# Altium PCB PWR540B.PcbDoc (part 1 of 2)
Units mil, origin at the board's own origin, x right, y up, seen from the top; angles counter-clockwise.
Board outline 2790 x 2490 mil, 4 copper layers (Top Layer, MidLayer1, MidLayer2, Bottom Layer), stack 95.6 mil thick; 144 components, 56 nets, 352 pads, 322 vias.
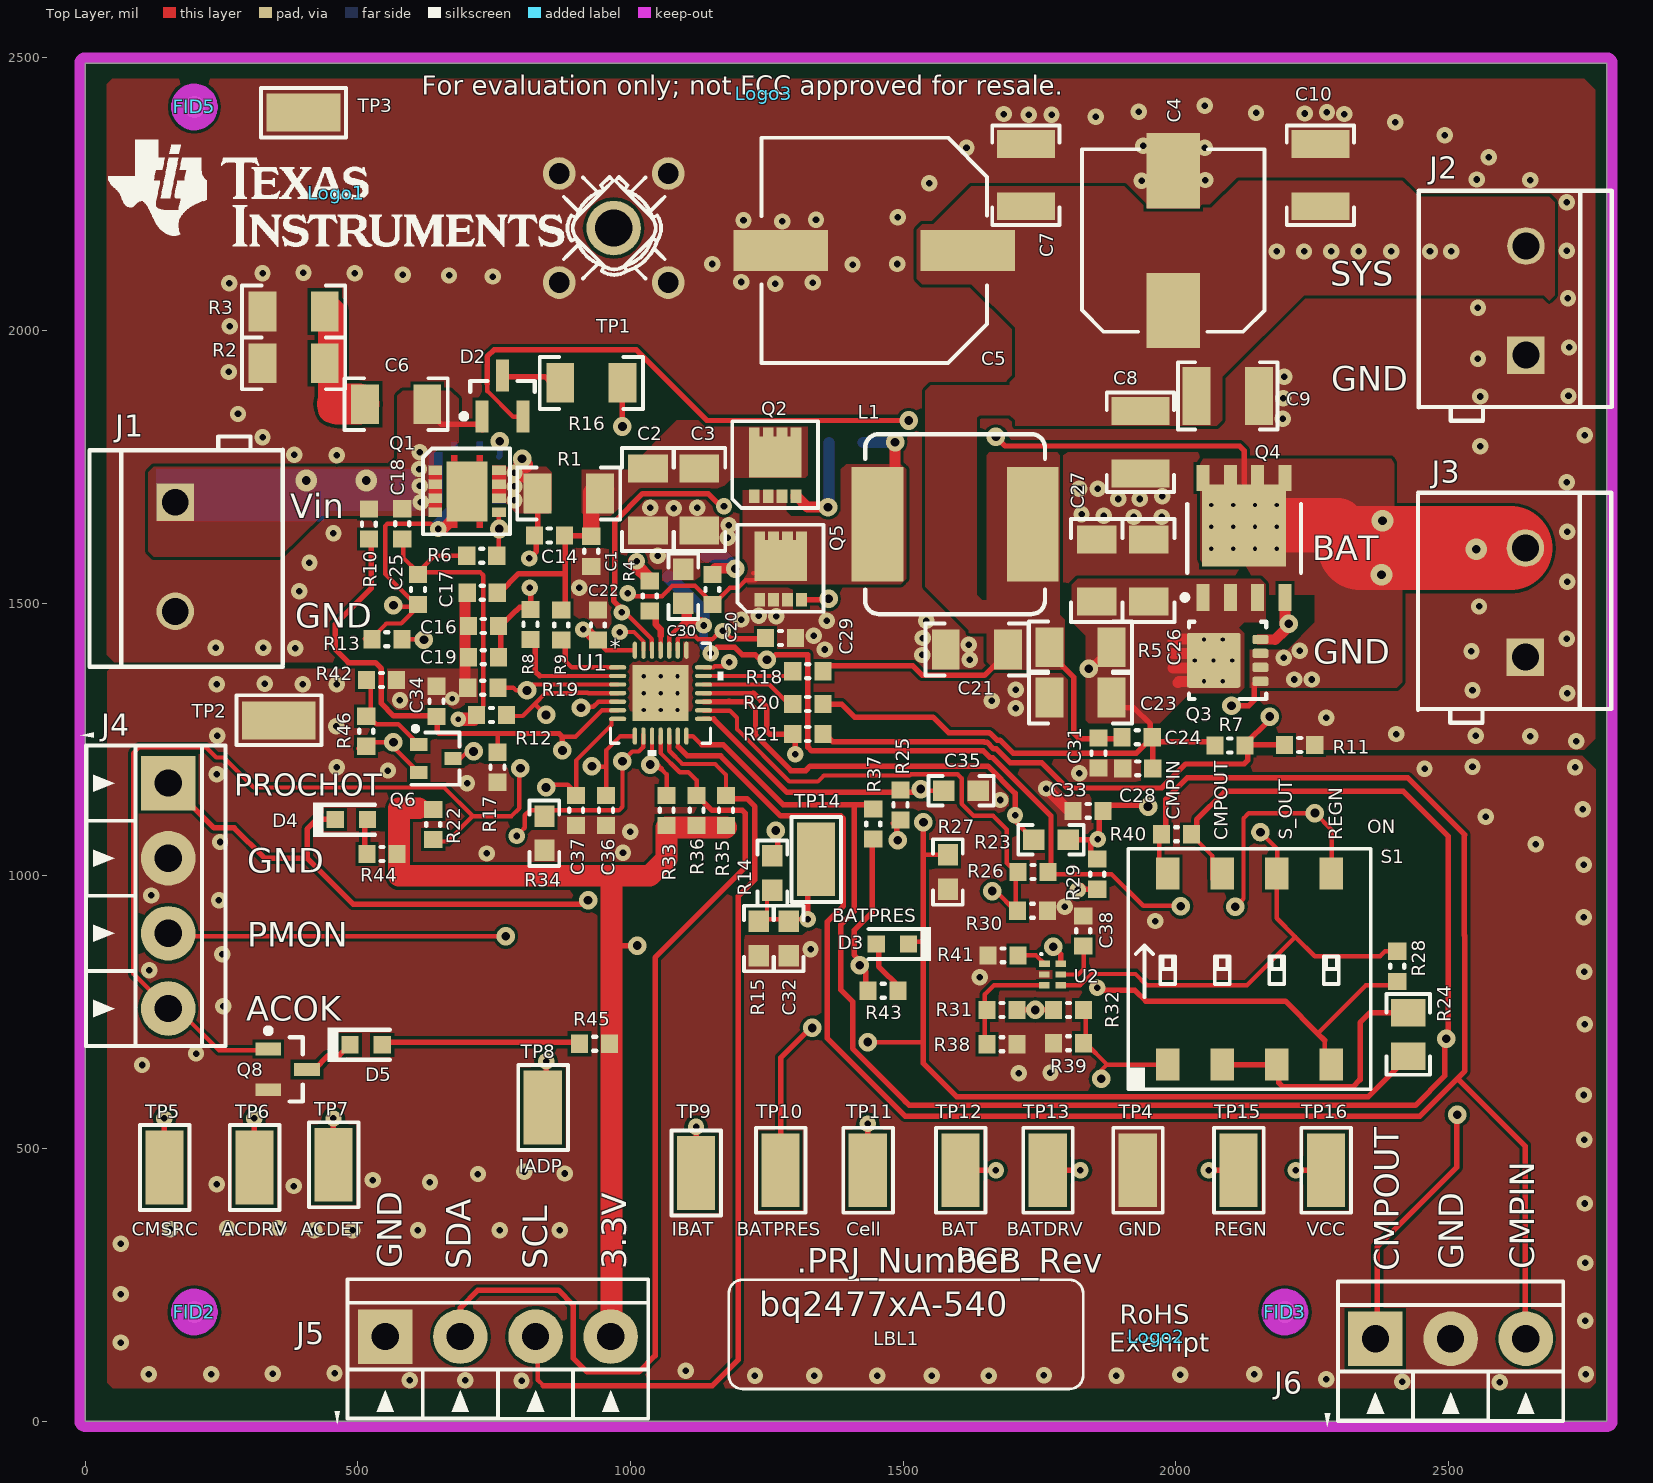
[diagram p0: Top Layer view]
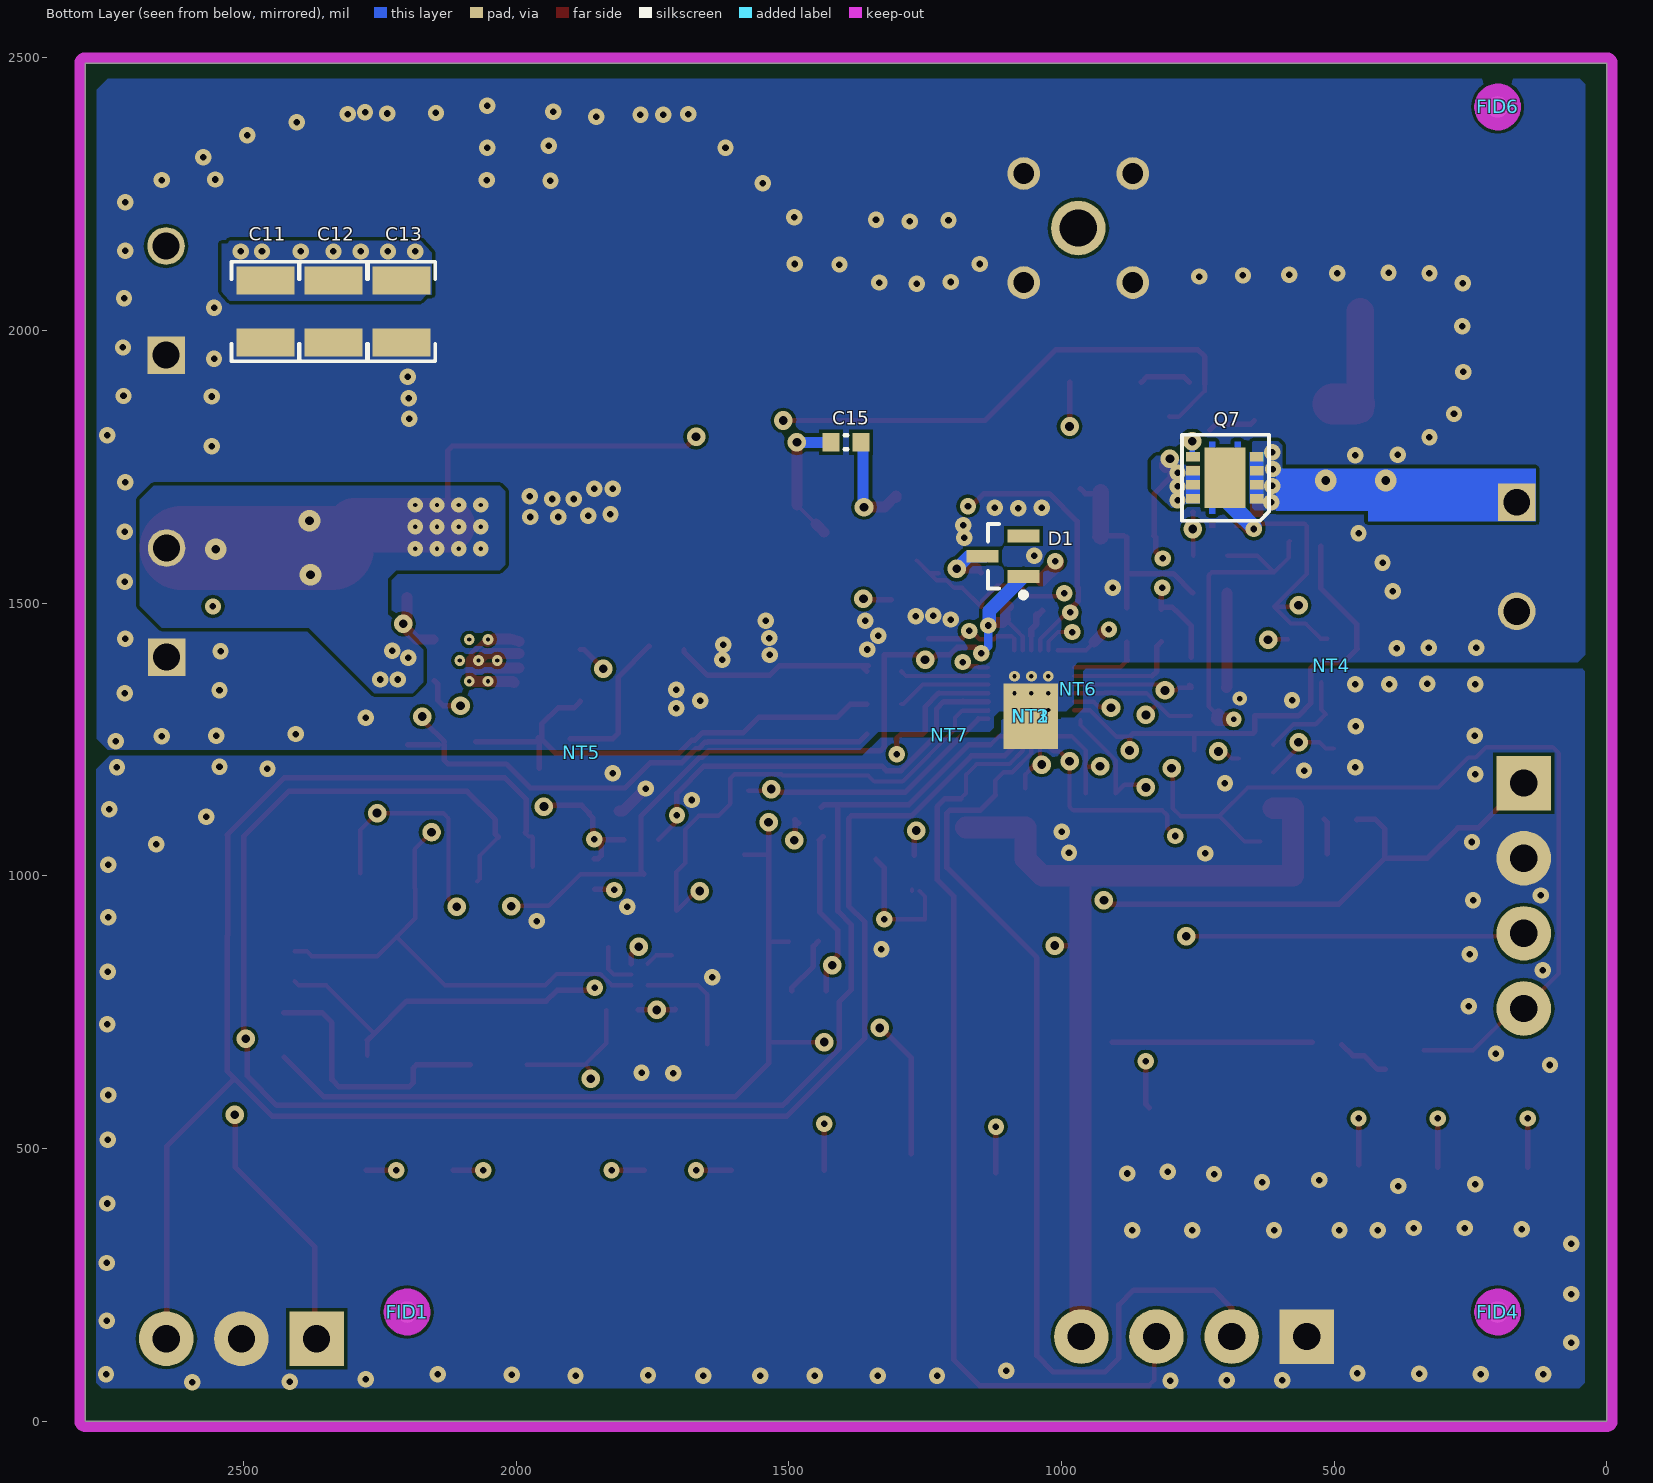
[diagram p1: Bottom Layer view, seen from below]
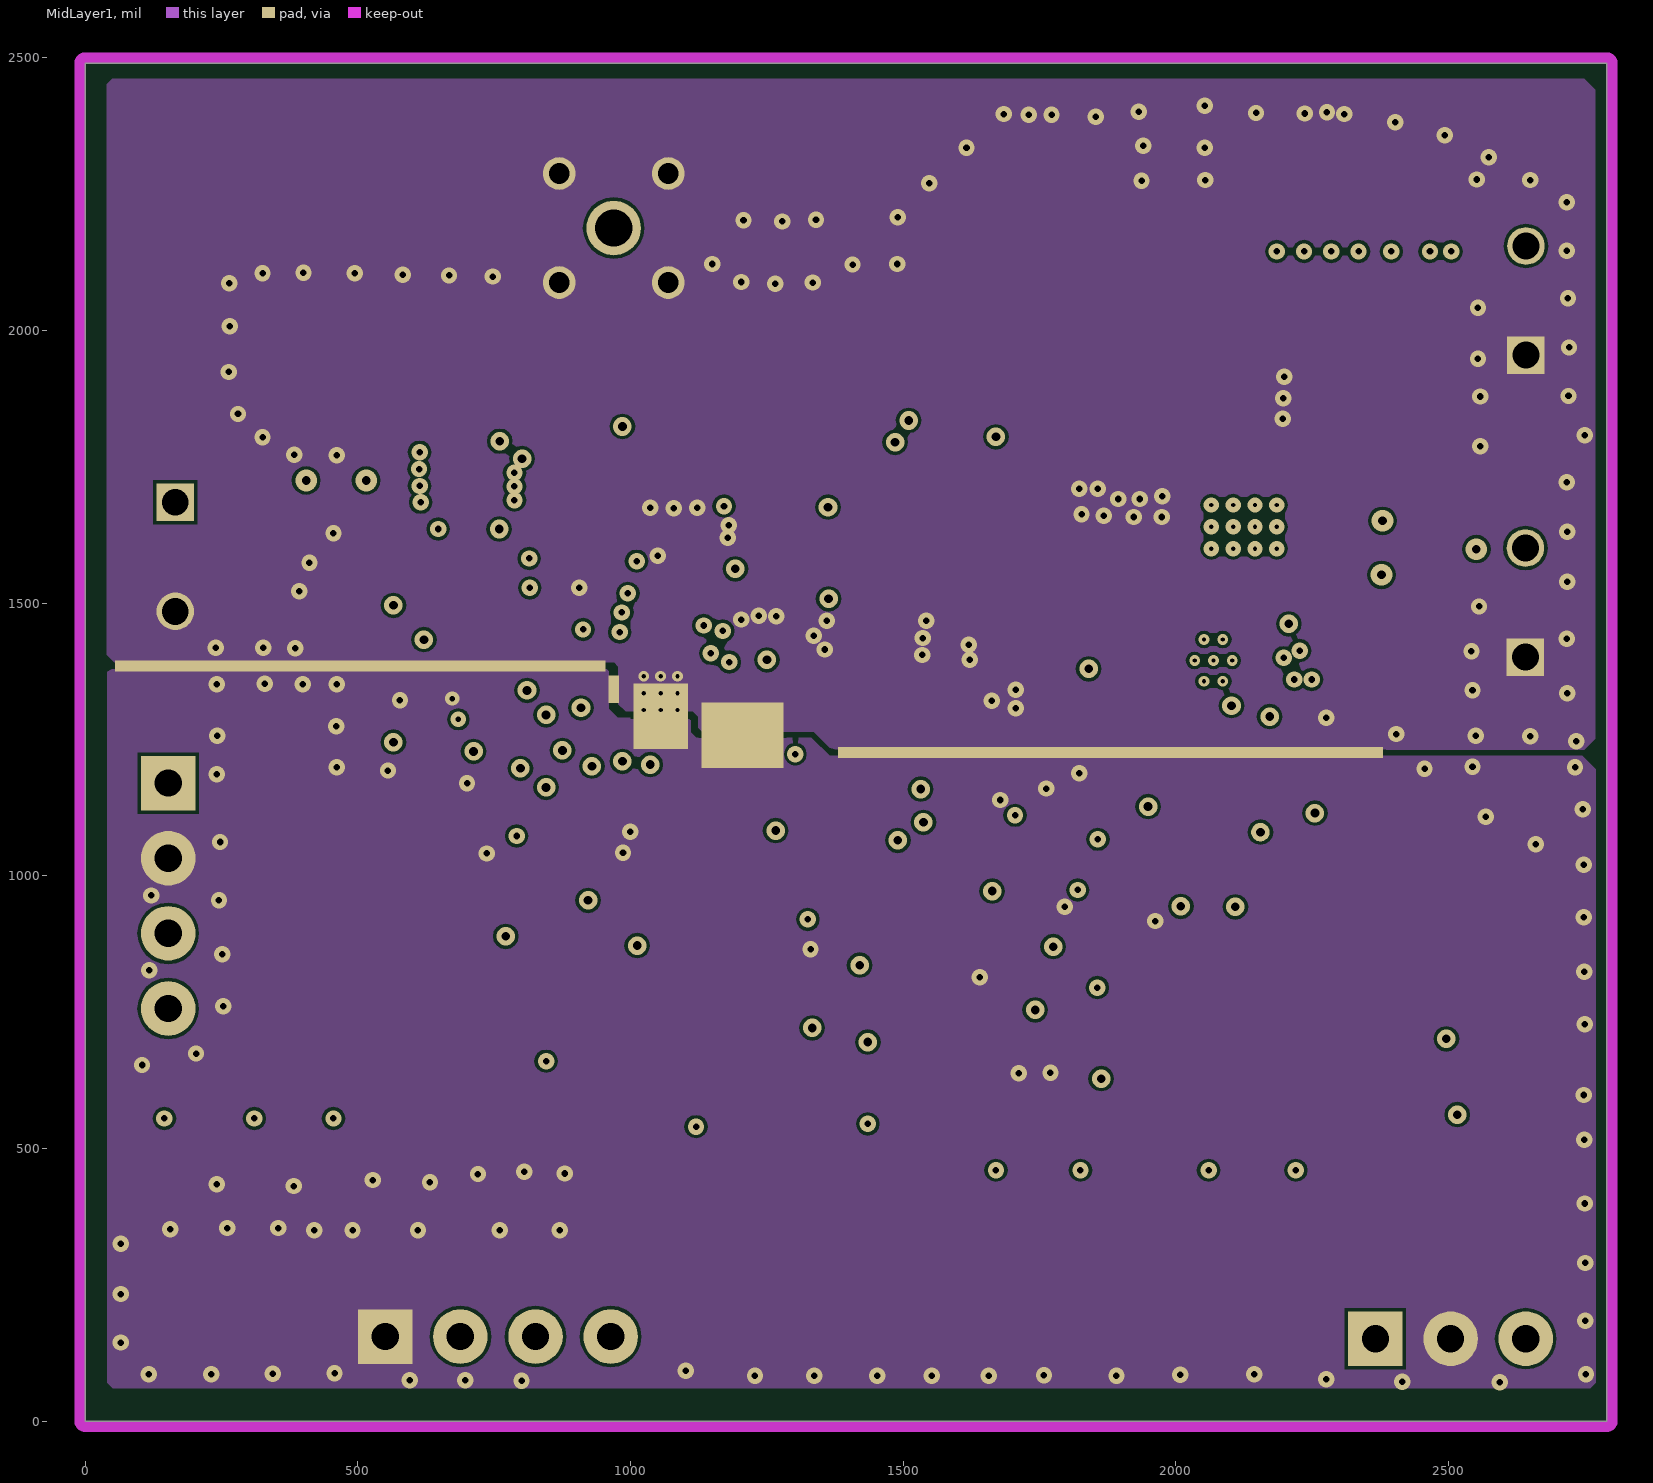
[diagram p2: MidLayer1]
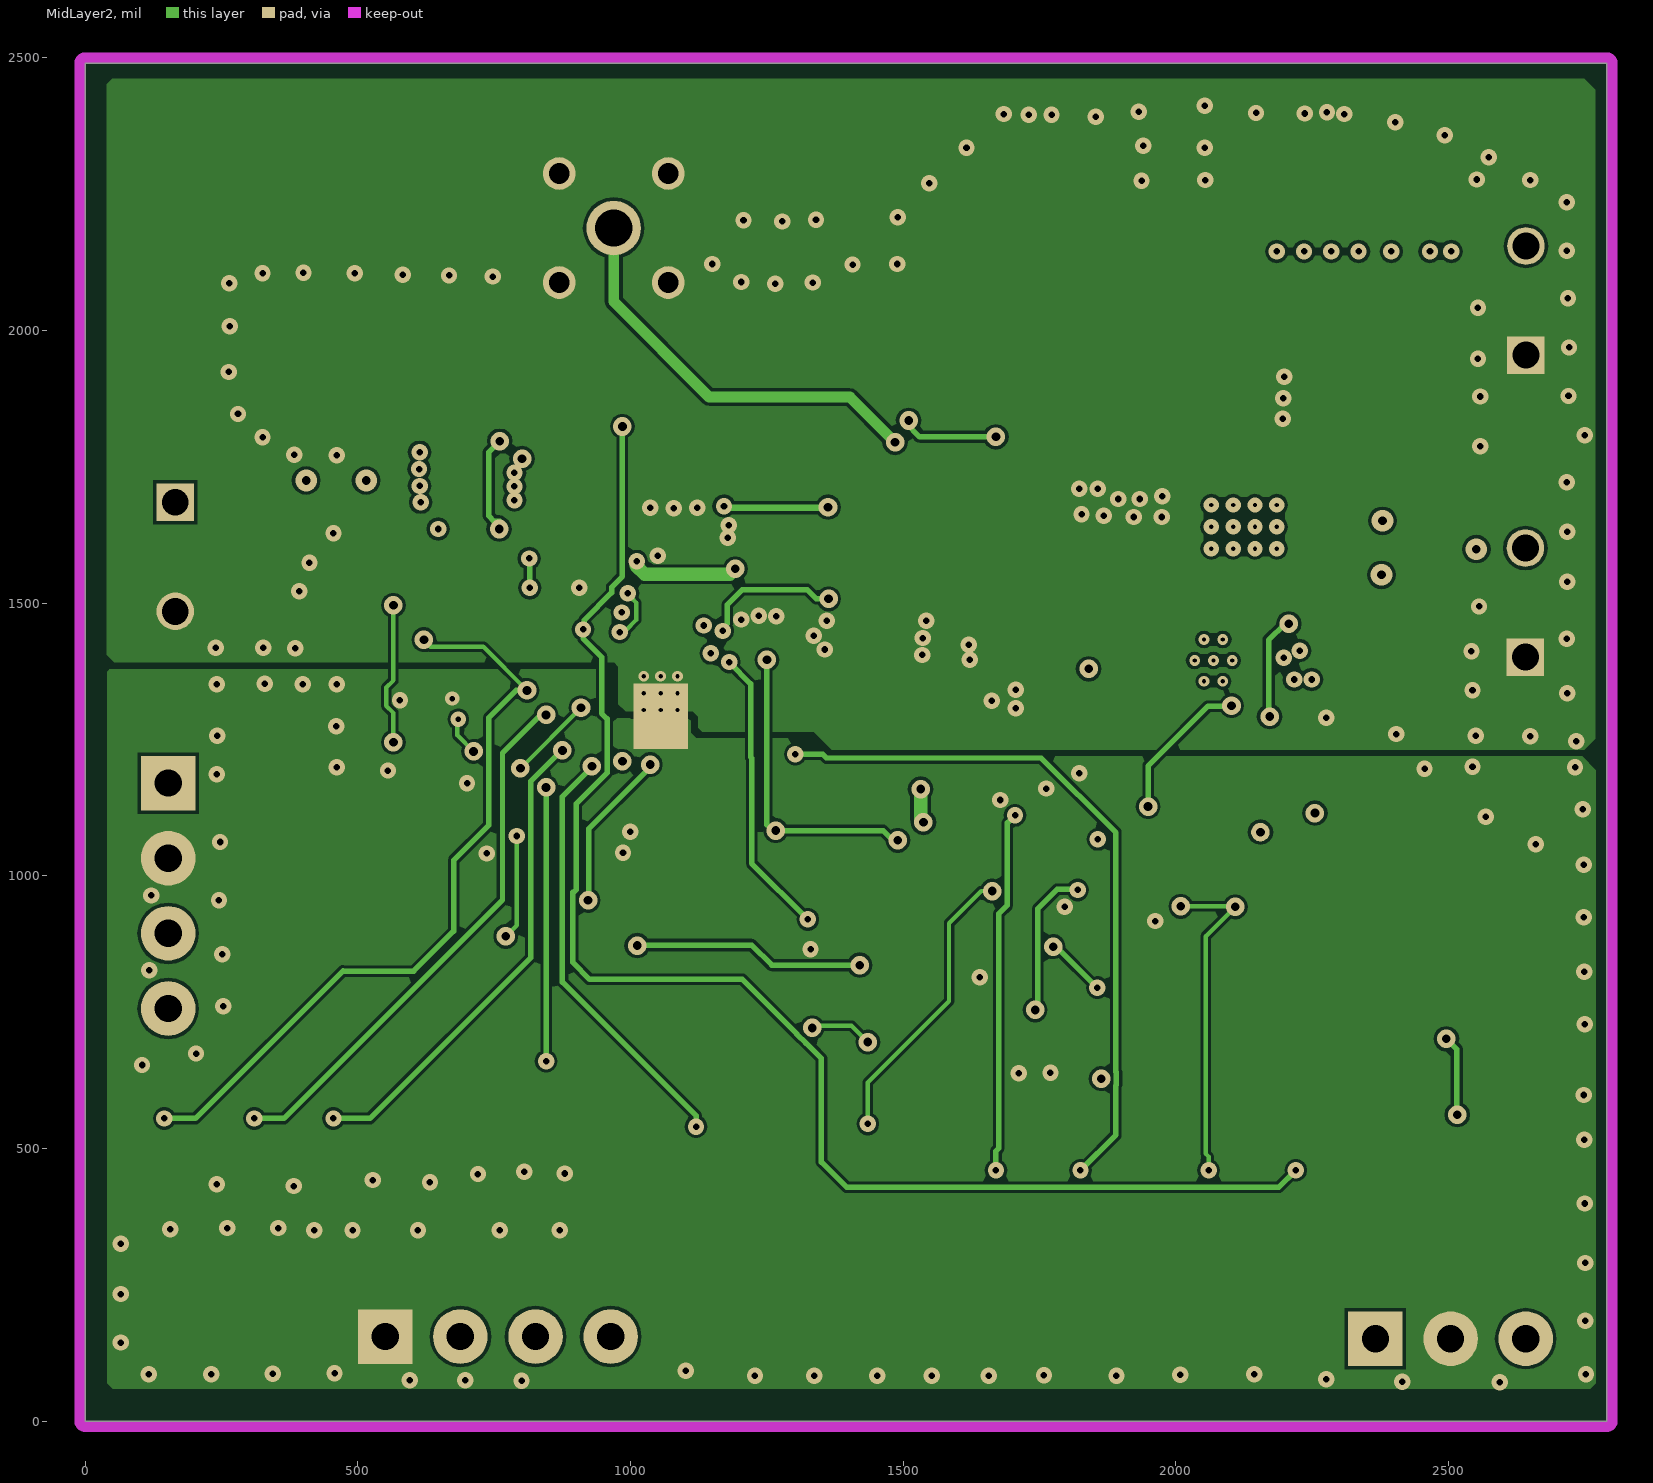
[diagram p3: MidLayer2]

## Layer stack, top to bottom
Top Solder: solder mask 0.4, Solder Resist, Dk 3.5
Top Layer: signal copper 2.8
Dielectric1: core 59.2, FR-4, Dk 4.8
MidLayer1: signal copper 2.8
Dielectric2: prepreg 12.6, FR-4, Dk 4.8
MidLayer2: signal copper 2.8
Dielectric3: core 12.6, FR-4, Dk 4.8
Bottom Layer: signal copper 2.8
Bottom Solder: solder mask 0.4, Solder Resist, Dk 3.5

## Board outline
0,0 0,2490 2790,2490 2790,0

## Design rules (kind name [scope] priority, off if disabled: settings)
AcuteAngle [All] p1: minimum=4.50000000000000E+0001 checktracksonly=FALSE
AssemblyTestPointUsage [All] p1: valid=2
AssemblyTestpoint [All] p1: testpointundercomponent=TRUE minsize=40 maxsize=100 preferedsize=30 minholesize=0 maxholesize=40 preferedholesize=12 testpointgrid=1 usegrid=TRUE gridtolerance=0.01 allowsidetop=TRUE allowsidebottom=TRUE
Clearance EVM [All] p1: gap=5.9 // TEST1
Clearance Clearance_BoardEdge_MountingHoles [OnCopper and InComponentClass('Mounting Holes') vs IsKeepOut] p2: gap=40
Clearance Clearance_BoardEdge_Poly [OnCopper and InPoly vs IsKeepOut] p3: gap=25
Clearance Clearance_BoardEdge [OnCopper and Not InComponentClass('Logo') and not InComponentClass('FiducialMark') and not InRegion(1000,500,4000,800) and Not IsKeepout vs IsKeepOut] p4: gap=25
Clearance [All] p5: gap=6
ComponentClearance ComponentClearance_NT [InComponent('NT*')] p1: gap=0 collisioncheckmode=3 verticalgap=0 showdistances=FALSE
ComponentClearance ComponentClearance_Logo [InComponentClass('Logo')] p2: gap=0 collisioncheckmode=3 verticalgap=0 showdistances=FALSE
ComponentClearance ComponentClearance_ScrewToNut [(HasFootprint('NY PMS 440 0025 PH')) vs (HasFootprint('Keystone_1902C'))] p3: gap=5 collisioncheckmode=3 verticalgap=10 showdistances=FALSE
ComponentClearance ComponentClearance_MountingHoles [InComponentClass('Mounting Holes')] p4: gap=50 collisioncheckmode=3 verticalgap=100000 showdistances=FALSE
ComponentClearance ComponentClearance_SmallPassives [HasFootprint('0201*') or HasFootprint('0402*') or HasFootprint('0508') or HasFootprint('0603*') or HasFootprint('0612') or HasFootprint('0805*') or HasFootprint('0815*') or HasFootprint('0830*') or HasFootprint('1206*') or HasFootprint('1210*') or HasFootprint('1808*') or HasFootprint('1812*') or HasFootprint('1825*') or HasFootprint('2010*') or HasFootprint('2220*') or HasFootprint('2225*') or HasFootprint('2512*') or HasFootprint('2728*') or HasFootprint('3518*') vs HasFootprint('0201*') or HasFootprint('0402*') or HasFootprint('0508') or HasFootprint('0603*') or HasFootprint('0612') or HasFootprint('0805*') or HasFootprint('0815*') or HasFootprint('0830*') or HasFootprint('1206*') or HasFootprint('1210*') or HasFootprint('1808*') or HasFootprint('1812*') or HasFootprint('1825*') or HasFootprint('2010*') or HasFootprint('2220*') or HasFootprint('2225*') or HasFootprint('2512*') or HasFootprint('2728*') or HasFootprint('3518*')] p5: gap=10 collisioncheckmode=3 verticalgap=10 showdistances=FALSE
ComponentClearance ComponentClearance_THtoSMT [IsThruComponent vs IsSMTComponent and not InComponentClass('Logo')] p6: gap=1 collisioncheckmode=3 verticalgap=0 showdistances=FALSE
ComponentClearance ComponentClearance_THtoTH [IsThruComponent vs IsThruComponent] p7: gap=10 collisioncheckmode=3 verticalgap=100000 showdistances=FALSE
ComponentClearance [All] p8: gap=10 collisioncheckmode=3 verticalgap=10 showdistances=FALSE
DiffPairsRouting [All] p1: maxlimit=100 minlimit=10 mostfreqgap=10 toplayer_minwidth=15 toplayer_maxwidth=15 toplayer_prefwidth=15 midlayer1_minwidth=15 midlayer1_maxwidth=15 midlayer1_prefwidth=15 midlayer2_minwidth=15 midlayer2_maxwidth=15 midlayer2_prefwidth=15 bottomlayer_minwidth=15 bottomlayer_maxwidth=15 bottomlayer_prefwidth=15 maxuncoupledlength=1000
FabricationTestPointUsage TestPointUsage [All] p1: valid=2 allowmultiple=FALSE
FabricationTestpoint Testpoint [All] p1: side=3 testpointundercomponent=TRUE minsize=40 maxsize=100 preferedsize=30 minholesize=0 maxholesize=40 preferedholesize=12 testpointgrid=1 allowsidetop=TRUE allowsidebottom=TRUE usegrid=TRUE gridtolerance=0.01
FanoutControl Fanout_LCC [IsLCC] p1: bgadir=Out bgaviamode=Centered fanoutstyle=Auto fanoutdirection=Alternating viagrid=1 // Fanout_LCC (Default Rule)
FanoutControl Fanout_BGA [IsBGA] p2: bgadir=Out bgaviamode=Centered fanoutstyle=Auto fanoutdirection=Alternating viagrid=1 // Fanout_BGA (Default Rule)
FanoutControl Fanout_Default [All] p4: bgadir=Out bgaviamode=Centered fanoutstyle=Auto fanoutdirection=Alternating viagrid=1 // Fanout_Default (Default Rule)
FanoutControl Fanout_Small [(CompPinCount < 5)] p5: bgadir=Out bgaviamode=Centered fanoutstyle=Auto fanoutdirection=OutThenIn viagrid=1 // Fanout_Small (Default Rule)
HoleSize [All] p1: absolutevalues=TRUE maxlimit=251 minlimit=7.8 maxpercent=80.000 minpercent=20.000
MinimumAnnularRing [All] p1: minimumring=5
MinimumSolderMaskSliver MinimumSolderMaskSliver_Logo [InComponentClass('Logo') vs InComponentClass('Logo')] p1: minsoldermaskwidth=0.7
MinimumSolderMaskSliver [All] p2: minsoldermaskwidth=3.9
PlaneConnect [All] p1: planeconnectstyle=Relief reliefexpansion=10 reliefentries=4 reliefconductorwidth=10 reliefairgap=10
PolygonConnect [All] p1: connectstyle=Direct reliefconductorwidth=10 reliefentries=4 polygonreliefangle="90 Angle" airgapwidth=10
RoutingVias [All] p1: holewidth=16 width=34 viastyle="Through Hole" minholewidth=7 minwidth=19 maxholewidth=40 maxwidth=65
SMDToCorner [All] p1 off: distance=30000
SilkToSilkClearance "SilkToSilkClearance_pbfree logo" [InComponent('Logo2') vs InComponent('Logo2')] p1: silktosilkclearance=0
SilkToSilkClearance [All] p2: silktosilkclearance=3
SilkToSolderMaskClearance SilkToSolderMaskClearance_fet [HasFootprint('TRANS_NexFET_Q3E')] p1: minsilkscreentomaskgap=0.5 clearancetoexposedcopper=TRUE
SilkToSolderMaskClearance [IsPad] p2: minsilkscreentomaskgap=3 clearancetoexposedcopper=TRUE
SolderMaskExpansion [All] p1: expansion=1
Width [All] p1: maxlimit=250 minlimit=7.8 preferedwidth=10 checkconnectedcopper=TRUE
15 further rules are at their usual default settings.

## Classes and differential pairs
component class Logo: Logo1
component class PWR540B_Hardware: FID1 FID2 FID3 FID4 FID5 FID6 LBL1 Logo1 Logo2 Logo3 ZZ1 ZZ2 ZZ3 ZZ4
component class PWR540B: C1 C2 C3 C4 C5 C6 C7 C8 C9 C10 C11 C12 C13 C14 C15 C16 C17 C18 C19 C20 C21 C22 C23 C24 C25 C26 C27 C28 C29 C30 C31 C32 C33 C34 C35 C36 C37 C38 C52 D1 D2 D3 D4 D5 J1 J2 J3 J4 J5 J6 L1 NT1 NT2 NT3 NT4 NT5 NT6 NT7 Q1 Q2 Q3 Q4 Q5 Q6 Q7 Q8 Q52 R1 R2 R3 R4 R5 R6 R7 R8 R9 R10 R11 R12 R13 R14 R15 R16 R17 R18 R19 R20 R21 R22 R23 R24 R25 R26 R27 R28 R29 R30 R31 R32 R33 R34 R35 R36 R37 R38 R39 R40 R41 R42 R43 R44 R45 R46 S1 TP1 TP2 TP3 TP4 TP5 TP6 TP7 TP8 TP9 TP10 TP11 TP12 TP13 TP14 TP15 TP16 U1 U2
component class FiducialMark: FID1 FID2 FID3 FID4 FID5 FID6
component class AssemblyNote: ZZ1 ZZ2 ZZ3 ZZ4
component class Label: LBL1

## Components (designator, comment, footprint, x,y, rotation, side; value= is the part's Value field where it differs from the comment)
C1 "GRM188R71E105KA12D" 0603L 928,1595 r270 top
C2 "GRM31CR61E106KA12L" 1206 1032,1690 r270 top
C3 "GRM31CR61E106KA12L" 1206 1126,1690 r270 top
C4 "20SVP100M" SM_RADIAL_8MM 1995,2165 r90 top
C5 "16SVP100M" SM_RADIAL_10AMM 1447,2147 r180 top
C6 "GRM31MR71E225KA93L" 1206 570,1865 r180 top
C7 "GRM32ER61E226KE15L" 1210 1725,2285 r90 top
C8 "GRM32ER61E226KE15L" 1210 1935,1795 r270 top
C9 "GRM32ER61E226KE15L" 1210 2095,1880 r0 top
C10 "GRM32ER61E226KE15L" 1210 2265,2285 r90 top
C11 "GRM32ER61E226KE15L" 1210 2460,2035 r270 bottom
C12 "GRM32ER61E226KE15L" 1210 2335,2035 r270 bottom
C13 "GRM32ER61E226KE15L" 1210 2210,2035 r270 bottom
C14 "GRM188R71E104KA01D" 0603L 851,1624 r0 top
C15 "GRM188R71E104KA01D" 0603L 1395,1795 r0 bottom
C16 "GRM188R71E104KA01D" 0603L 730,1458 r180 top
C17 "GRM188R71E104KA01D" 0603L 728,1519 r180 top
C18 "GRM188R71E222KA01D" 0603L 581,1645.47 r270 top
C19 "GRM188R71E105KA12D" 0603L 730,1401 r180 top
C20 "GRM188R71E473KA01D" 0603L 1150,1525 r270 top
C21 "GRM31CR61E106KA12L" 1206 1635,1415 r180 top
C22 "GRM188R71E105KA12D" 0603L 940,1460 r90 top
C23 "GRM31CR61E106KA12L" 1206 1825,1327 r180 top
C24 "GRM188R71E104KA01D" 0603L 1929,1254 r0 top
C25 "GRM188R71E104KA01D" 0603L 610,1525 r90 top
C26 "GRM31CR61E106KA12L" 1206 1950,1560 r90 top
C27 "GRM31CR61E106KA12L" 1206 1855,1560 r90 top
C28 "GRM188R71E104KA01D" 0603L 1930,1197 r180 top
C29 "GRM1885C1H471JA01D" 0603L 1275,1436 r0 top
C30 "GRM188R71E105KA12D" 0603 1096.77,1531 r90 top
C31 "GRM188R71E104KA01D" 0603L 1858,1225 r270 top
C32 "GRM188R71E103KA01D" 0603 1290,885 r90 top
C33 "GRM188R71E104KA01D" 0603L 1839,1119 r180 top
C34 "GRM188R71E104KA01D" 0603L 644,1320 r90 top
C35 "GRM188R71E103KA01D" 0603 1606,1156 r0 top
C36 "C0603C101J5GAC" 0603L 955,1120 r270 top
C37 "C0603C101J5GAC" 0603L 900,1120 r270 top
C38 "C0603C101J5GAC" 0603L 1830,899 r90 top
D1 "BAT54-7-F" SOT-23 1107,1586 r0 bottom
D2 "BAT54C-7-F" SOT-23 765,1880 r90 top
D3 "LTST-C190GKT" LED_LTST-C190 1480,875 r0 top
D4 "LTST-C190GKT" LED_LTST-C190 488,1103 r180 top
D5 "LTST-C190GKT" LED_LTST-C190 515,690 r180 top
FID1 "Fiducial" Fiducial10-20 2200,200 r90 bottom
FID2 "Fiducial" Fiducial10-20 200,200 r90 top
FID3 "Fiducial" Fiducial10-20 2200,200 r90 top
FID4 "Fiducial" Fiducial10-20 200,200 r90 bottom
FID5 "Fiducial" Fiducial10-20 200,2410 r90 top
FID6 "Fiducial" Fiducial10-20 200,2410 r90 bottom
J1 "ED120/2DS" CONN_ED120-2DS 165,1585 r180 top
J2 "ED120/2DS" CONN_ED120-2DS 2642,2055 r0 top
J3 "ED120/2DS" CONN_ED120-2DS 2641,1501 r0 top
J4 "ED555/4DS" TERM_BLK_ED555-4DS 152,1170 r270 top
J5 "ED555/4DS" TERM_BLK_ED555-4DS 550,155 r0 top
J6 "ED555/3DS" TERM_BLK_ED555-3DS 2366,151 r0 top
L1 "IHLP3232DZER2R2M01" IHLP-3232DZ 1595,1645 r0 top
LBL1 "Size: 0.65\" x 0.20 \"" Label_650x200 1505,159 r0 top
Logo1 "Texas Instruments" TI_Stacked_Overlay_Small 460,2252 r0 top
Logo2 "EU RoHS Exempt Logo" EURoHS_Exempt_60mil_Stacked 1964,155 r0 top
Logo3 "FCC disclaimer" FCC_disclaimer 1244,2434 r0 top
NT1 "Net-Tie" Net-Tie_20milWide_60milLong#1 1055,1293 r90 bottom net-tie
NT2 "Net-Tie" Net-Tie_20milWide_60milLong#2 1056,1293 r90 bottom net-tie
NT3 "Net-Tie" Net-Tie_20milWide_60milLong#3 1055,1293 r90 bottom net-tie
NT4 "Net-Tie" Net-Tie_20milWide_60milLong#4 504,1385 r90 bottom net-tie
NT5 "Net-Tie" Net-Tie_20milWide_60milLong#5 1880,1226 r90 bottom net-tie
NT6 "Net-Tie" Net-Tie_20milWide_60milLong#6 969,1342 r0 bottom net-tie
NT7 "Net-Tie" Net-Tie_20milWide_60milLong#7 1205,1258 r90 bottom net-tie
Q1 "CSD87312Q3E" TRANS_NexFET_Q3E 700,1705 r0 top
Q2 "CSD17308Q3" TRANS_NexFET_Q3 1265,1755 r90 top
Q3 "CSD25401Q3" DQG0008A 2095,1395 r180 top
Q4 "SI7139DP-T1-GE3" PowerPAK_SO-8 2125,1620 r90 top
Q5 "CSD17308Q3" TRANS_NexFET_Q3 1275,1565 r90 top
Q6 "BSS138W-7-F" SOT-323 643,1215 r0 top
Q7 "CSD87312Q3E" TRANS_NexFET_Q3E 700,1730 r0 bottom
Q8 "2N7002ET1G" SOT-23L 371,645 r0 top
R1 "WSLP1206R0100FEA" 1206 886.46,1701.02 r0 top
R2 "CRCW12063R90JNEA" 1206 382,1940 r0 top
R3 "CRCW12063R90JNEA" 1206 382,2035 r0 top
R4 "CRCW06030000Z0EA" 0603L 1035,1513 r90 top
R5 "WSLP1206R0100FEA" 1206 1825,1419 r0 top
R6 "CRCW06034R70JNEA" 0603L 727,1587 r0 top
R7 "CRCW060310M0JNEA" 0603L 2099,1239 r180 top
R8 "CRCW06030000Z0EA" 0603L 816.46,1461.02 r90 top
R9 "CRCW06030000Z0EA" 0603L 873,1460 r90 top
R10 "RC0603FR-07430KL" 0603L 520,1645 r90 top
R11 "CRCW060310M0JNEA" 0603L 2227,1240 r180 top
R12 "CRCW06034K02FKEA" 0603L 745,1295 r180 top
R13 "CRCW06034K02FKEA" 0603L 553,1434 r180 top
R14 "CRCW0603316KFKEA" 0603 1260,1005 r90 top
R15 "CRCW0603100KFKEA" 0603 1235,885 r270 top
R16 "CRCW120610R0FKEA" 1206 928,1904 r180 top
R17 "CRCW060366K5FKEA" 0603L 756,1199 r90 top
R18 "CRCW06030000Z0EA" 0603L 1325.02,1375 r0 top
R19 "CRCW06030000Z0EA" 0603L 729,1345 r180 top
R20 "CRCW06030000Z0EA" 0603L 1325.02,1315 r0 top
R21 "CRCW06030000Z0EA" 0603L 1325.02,1260 r0 top
R22 "CRCW060310K0FKEA" 0603L 638,1094 r90 top
R23 "CRCW060310R0FKEA" 0603 1771,1066 r0 top
R24 "CRCW08050000Z0EA" 0805_HV 2426,709 r90 top
R25 "CRCW060310M0JNEA" 0603L 1495,1130 r90 top
R26 "CRCW060310M0JNEA" 0603L 1738,1007 r0 top
R27 "CRCW0603100KFKEA" 0603 1582,1007 r90 top
R28 "CRCW060310K0FKEA" 0603L 2406,834 r270 top
R29 "CRCW06030000Z0EA" 0603L 1856,1003 r90 top
R30 "CRCW060310M0JNEA" 0603L 1737,936 r180 top
R31 "CRCW0603499KFKEA" 0603L 1681,754 r0 top
R32 "CRCW0603140KFKEA" 0603L 1803,754 r180 top
R33 "CRCW060310K0FKEA" 0603L 1066,1120 r270 top
R34 "CRCW060330K1FKEA" 0603 842,1078 r270 top
R35 "CRCW060310K0FKEA" 0603L 1175,1120 r270 top
R36 "CRCW060310K0FKEA" 0603L 1121,1120 r270 top
R37 "CRCW060310K0FKEA" 0603L 1445,1095 r90 top
R38 "CRCW060349K9FKEA" 0603L 1681,691 r180 top
R39 "CRCW0603100KFKEA" 0603L 1803,693 r0 top
R40 "CRCW06033M00JNEA" 0603L 2001,1076 r180 top
R41 "CRCW0603100KFKEA" 0603L 1683,854 r0 top
R42 "CRCW06031M00FKEA" 0603L 543,1359 r180 top
R43 "CRCW06032K00FKEA" 0603L 1463,789 r0 top
R44 "CRCW06032K00FKEA" 0603L 544,1040 r180 top
R45 "CRCW06032K00FKEA" 0603L 934,692 r0 top
R46 "CRCW06033M01FKEA" 0603L 515,1265 r270 top
S1 "A6S-4104-H" SW_A6S-4104-H 2135,829 r90 top
TP1 "131-5031-00" Tek_131-5031-00 969,2188 r0 top
TP2 "5015" Testpoint_Keystone_Miniature 355,1285 r180 top
TP3 "5015" Testpoint_Keystone_Miniature 400,2400 r0 top
TP4 "5015" Testpoint_Keystone_Miniature 1930,460 r90 top
TP5 "5015" Testpoint_Keystone_Miniature 145,465 r90 top
TP6 "5015" Testpoint_Keystone_Miniature 310,465 r90 top
TP7 "5015" Testpoint_Keystone_Miniature 455,470 r90 top
TP8 "5015" Testpoint_Keystone_Miniature 838.89,575 r90 top
TP9 "5015" Testpoint_Keystone_Miniature 1120,455 r90 top
TP10 "5015" Testpoint_Keystone_Miniature 1275,460 r90 top
TP11 "5015" Testpoint_Keystone_Miniature 1435,460 r90 top
TP12 "5015" Testpoint_Keystone_Miniature 1605,460 r90 top
TP13 "5015" Testpoint_Keystone_Miniature 1765,460 r90 top
TP14 "5015" Testpoint_Keystone_Miniature 1340,1030 r90 top
TP15 "5015" Testpoint_Keystone_Miniature 2115,460 r90 top
TP16 "5015" Testpoint_Keystone_Miniature 2275,460 r90 top
U1 "bq2477xRUY" RUY0028A 1055,1335 r0 top
U2 "TPS3898ADRY" DRY0006A 1774,819 r0 top
ZZ1 "This Assembly Note is for PCB labels only" AssemblyNoteLabel 185,3338 r0 top
ZZ2 "These assemblies must be clean and free from flux and all contaminants. Use of no clean flux is not acceptable." AssemblyNote 185,3140.56 r0 top
ZZ3 "These assemblies are ESD sensitive, ESD precautions shall be observed." AssemblyNote 185,3229.11 r0 top
ZZ4 "These assemblies must comply with workmanship standards IPC-A-610 Class 2., unless otherwise specified." AssemblyNote 185,3052 r0 top

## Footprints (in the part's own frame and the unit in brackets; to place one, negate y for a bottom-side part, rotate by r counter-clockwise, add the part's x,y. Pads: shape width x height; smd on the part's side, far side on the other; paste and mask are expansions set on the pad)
0603 [mm] "0603 from SM-752 data"
  rect 1x0.95 smd: 1(-0.8,0) 2(0.8,0)
  silkscreen extent -1.52,-0.69 1.52,0.69, body extent -0.87,-0.47 0.87,0.47, height 0.85
0603L [mm] "0603 from SM-752 data"
  rect 0.8x0.85 smd: 1(-0.7,0) 2(0.7,0)
  silkscreen extent -0.07,-0.33 0.07,0.33, body extent -0.87,-0.47 0.87,0.47, height 0.85
0805_HV [mil] "0805 with 30mil clearance between pads"
  rect 50x63 smd: 1(-40,0) 2(40,0)
  silkscreen extent -74,-40 74,40, body extent -43,-29 43,29, height 43
1206 [mm] "1206 from SM-752 data"
  rect 1.3x1.85 smd: 1(-1.45,0) 2(1.45,0)
  silkscreen extent -2.4,-1.21 2.4,1.21, body extent -1.7,-0.9 1.7,0.9, height 1.35
1210 [mm] "1210 from SM-752 data"
  rect 1.3x2.7 smd: 1(-1.45,0) 2(1.45,0)
  silkscreen extent -2.32,-1.57 2.32,1.57, body extent -1.7,-1.35 1.7,1.35, height 1.35
AssemblyNote [mil] "Assembly Note"
AssemblyNoteLabel [mil] "Assembly Note for PCB Labels"
CONN_ED120-2DS [mm] "ONSHORE"
  rect 1.75x1.75 hole 1.25: 1(0,-2.54)
  round 1.75 hole 1.25: 2(0,2.54)
  silkscreen extent -5,-5.6 4,5.12, body extent -5,-5.6 4.15,5.12, height 13.1
DQG0008A [mm] "SMD, 8-Leads, Body 3.3x3.3mm, Pitch 0.65mm"
  rrect45% 0.75x0.44 smd paste-0.05 mask-0.05: 1(-1.525,0.975) 2(-1.525,0.325) 3(-1.525,-0.325) 4(-1.525,-0.975) 5(1.525,-0.975) 6(1.525,-0.325) 7(1.525,0.325) 8(1.525,0.975)
  rrect15% 0.676x1.125 on Top Paste: 9(-0.212,0.662) 9(-0.212,-0.663) 9(0.664,0.662) 9(0.664,-0.663)
  rrect6% 1.775x2.45 on Top Solder: 9(0.327,0)
  rrect8% 2.5x2.55 smd paste-1.5 mask-1.5: 9(0.65,0)
  rrect29% 0.5x0.34 on Top Solder: 9(1.175,0.975) 9(1.175,-0.325) 9(1.175,0.325) 9(1.175,-0.975)
  silkscreen extent -1.8,-1.8 1.8,1.8, body extent -1.65,-1.65 1.65,1.65, height 1.1
DRY0006A [mm] "PSON, 6-Leads, Body 1x1.45mm, Pitch 0.5mm, TI Recommended"
  rect 0.52x0.3 smd paste+0: 1(-0.385,0.5)
  rect 0.49x0.3 smd paste+0: 2(-0.385,0) 3(-0.385,-0.5) 4(0.385,-0.5) 5(0.385,0) 6(0.385,0.5)
  silkscreen extent -0.57,0.9 -0.48,1, body extent -0.53,-0.75 0.53,0.75, height 0.6
EURoHS_Exempt_60mil_Stacked [mil] "EU RoHS Exempt symbol"
FCC_disclaimer [mil]
Fiducial10-20 [mm]
  round 1 smd mask+0.5: 1(0,0)
  Top Layer keep-out circle w1.178: c0,0 r0.5
IHLP-3232DZ [mil] "VISHAY"
  rect 95x210 smd: 1(-142.5,0) 2(142.5,0)
  silkscreen extent -165,-165 165,165, body extent -162,-162 162,162, height 158
Label_650x200 [mil] "Thermal Transfer Label"
  silkscreen extent -325,-100 325,100, body extent -325,-100 325,100, height 1
LED_LTST-C190 [mm] "Lite-On"
  rect 0.8x0.8 smd: 1(-0.75,0) 2(0.75,0)
  silkscreen extent -1.1,-0.8 1.8,0.8, body extent -0.85,-0.45 0.85,0.45, height 0.9
Net-Tie_20milWide_60milLong#1 [mil] "20mil net tie, no solder mask opening, no solder paste"
  rect 60x100 on Mid2 paste-10 mask-10: 1(-30,0) 2(30,0)
Net-Tie_20milWide_60milLong#2 [mil] "20mil net tie, no solder mask opening, no solder paste"
  rect 60x100 smd paste-50 mask-50: 1(-30,0) 2(30,0)
Net-Tie_20milWide_60milLong#3 [mil] "20mil net tie, no solder mask opening, no solder paste"
  rect 60x100 on Mid1 paste-10 mask-10: 1(-30,0) 2(30,0)
Net-Tie_20milWide_60milLong#4 [mil] "20mil net tie, no solder mask opening, no solder paste"
  rect 10x900 on Mid1 paste-10 mask-10: 1(-5,0) 2(5,0)
Net-Tie_20milWide_60milLong#5 [mil] "20mil net tie, no solder mask opening, no solder paste"
  rect 10x1000 on Mid1 paste-10 mask-10: 1(-5,0) 2(5,0)
Net-Tie_20milWide_60milLong#6 [mil] "20mil net tie, no solder mask opening, no solder paste"
  rect 10x50 on Mid1 paste-10 mask-10: 1(-5,0) 2(5,0)
Net-Tie_20milWide_60milLong#7 [mil] "20mil net tie, no solder mask opening, no solder paste"
  rect 60x150 on Mid1 paste-10 mask-10: 1(-30,0) 2(30,0)
PowerPAK_SO-8 [mil] "Vishay PowerPAK SO-8, Body 5.3x6.0mm (max), Pitch 1.27mm, IPC Medium Density"
  rect 50x24 smd mask+2.99: 1(-109.5,75) 2(-109.5,25) 3(-109.5,-25) 4(-109.5,-75)
  rect 48x24 smd mask+2.99: 5(109.5,-75) 8(109.5,75)
  rect 48x24 smd paste-12 mask+2.99: 6(109.5,-25) 7(109.5,25)
  rect 150x154 smd paste-75 mask+2.99: 9(22.5,0)
  silkscreen extent -114,-104 62,113, body extent -121,-102 121,102, height 43
RUY0028A [mm] "0.40mm pitch"
  oval 0.8x0.2 smd: 1(-2,1.2) 2(-2,0.8) 3(-2,0.4) 4(-2,0) 5(-2,-0.4) 6(-2,-0.8) 7(-2,-1.2) 15(2,-1.2) 16(2,-0.8) 17(2,-0.4) 18(2,0) 19(2,0.4) 20(2,0.8) 21(2,1.2)
  oval 0.2x0.8 smd: 8(-1.2,-2) 9(-0.8,-2) 10(-0.4,-2) 11(0,-2) 12(0.4,-2) 13(0.8,-2) 14(1.2,-2) 22(1.2,2) 23(0.8,2) 24(0.4,2) 25(0,2) 26(-0.4,2) 27(-0.8,2) 28(-1.2,2)
  rect 2.6x2.6 smd paste-1.287 mask-1.287: 29(0,0)
  silkscreen extent -2.33,-2.91 2.91,2.33, body extent -2.07,-2.07 2.07,2.07, height 0.81
SM_RADIAL_8MM [mm] "Nichicon 8x10"
  rect 3.5x2.5 smd: 1(-3.25,0) 2(3.25,0)
  silkscreen extent -4.25,-4.25 4.25,4.25, body extent -4.25,-4.25 4.25,4.25, height 10.5
SM_RADIAL_10AMM [mm] "10 x 7.9mm:  Sanyo Oscon F8"
  rect 4.4x1.9 smd: 1(-4.35,0) 2(4.35,0)
  silkscreen extent -5.25,-5.25 5.25,5.25, body extent -5.25,-5.25 5.25,5.25, height 8
SOT-23 [mm] "SOT23, 3-Leads, Body 2.9x1.3mm, Pitch 0.95mm, Lead Span 2.5mm, IPC Medium Density"
  rect 1.5x0.6 smd: 1(-0.95,0.95) 2(-0.95,-0.95) 3(0.95,0)
  silkscreen extent -1.07,-1.5 0.7,1.92, body extent -1.16,-1.45 1.21,1.45, height 1
SOT-23L [mm] "SOT23, 3-Leads, Body 2.9x1.3mm, Pitch 0.95mm, Lead Span 2.5mm, IPC High Density"
  rect 1.2x0.6 smd: 1(-0.9,0.95) 2(-0.9,-0.95) 3(0.9,0)
  silkscreen extent -1.02,-1.5 0.7,1.92, body extent -1.16,-1.45 1.21,1.45, height 1
SOT-323 [mm] "Zetex recommended land pattern.  March 2007"
  rect 0.8x0.6 smd: 1(-0.8,0.65) 2(-0.8,-0.65) 3(0.8,0)
  silkscreen extent -1.14,-1.22 1.09,1.49, body extent -1.13,-1.13 1.12,1.12, height 1.13
SW_A6S-4104-H [mm] "Omron recommended land pattern"
  rect 1.5x1.1 smd: 1(-4.45,3.81) 2(-4.45,1.27) 3(-4.45,-1.27) 4(-4.45,-3.81) 5(4.45,-3.81) 6(4.45,-1.27) 7(4.45,1.27) 8(4.45,3.81)
  silkscreen extent -5.6,-5.65 5.6,5.65, body extent -3.2,-5.65 3.2,5.65, height 4.5
Tek_131-5031-00 [mil] "Tektronix cold nose probe"
  round 100 hole 68: 1(0,0)
  round 60 hole 38: 2(-100,100) 3(-100,-100) 4(100,-100) 5(100,100)
  silkscreen extent -92,-93 94,94, body extent -206,-206 206,206, height 351
TERM_BLK_ED555-3DS [mm]
  rect 2.54x2.54 hole 1.27: 1(0,0)
  round 2.54 hole 1.27: 2(3.5,0) 3(7,0)
  silkscreen extent -2.36,-4.09 8.75,2.67, body extent -1.75,-3.83 8.75,2.67, height 8.2
TERM_BLK_ED555-4DS [mm]
  rect 2.54x2.54 hole 1.27: 1(0,0)
  round 2.54 hole 1.27: 2(3.5,0) 3(7,0) 4(10.5,0)
  silkscreen extent -2.36,-4.09 12.25,2.67, body extent -1.75,-3.8 12.25,2.7, height 8.2
Testpoint_Keystone_Miniature [mil] "Miniature SMT test point"
  rect 135x70 smd: 1(0,0)
  silkscreen extent -78,-46 78,45, body extent -52,-20 52,20, height 61
TI_Stacked_Overlay_Small [mil]
  silkscreen extent -418,-98 418,98
TRANS_NexFET_Q3 [mm] "TI recommended land pattern (nominal) M0143-01"
  rect 0.63x0.5 smd: 1(-1.49,0.975) 2(-1.49,0.325) 3(-1.49,-0.325) 4(-1.49,-0.975)
  rect 0.41x0.5 smd: 5(1.49,-0.975) 6(1.49,-0.325) 7(1.49,0.325) 8(1.49,0.975)
  rect 1.9x2.45 smd paste-0.05 mask+0.076: 9(0.335,0)
  silkscreen extent -2.05,-2 2,2, body extent -1.76,-1.7 1.66,1.7, height 1.11
TRANS_NexFET_Q3E [mm] "TI recommended land pattern M0143-01"
  rect 0.65x0.44 smd paste-0.05: 1(-1.48,0.975) 2(-1.48,0.325) 3(-1.48,-0.325) 4(-1.48,-0.975) 5(1.48,-0.975) 6(1.48,-0.325) 7(1.48,0.325) 8(1.48,0.975)
  rect 1.9x2.8 smd paste-5 mask+0.06: 9(0,0)
  Top Layer region: -1.805,-1.195 -1.155,-1.195 -1.155,1.195 -1.805,1.195
  Top Layer region: 1.155,-0.545 1.805,-0.545 1.805,1.195 1.155,1.195
  Top Layer region: -0.74,-1.7 -0.44,-1.7 -0.44,-1.4 -0.74,-1.4
  Top Layer region: 0.44,-1.7 0.74,-1.7 0.74,-1.4 0.44,-1.4
  Top Layer region: -0.74,1.4 -0.44,1.4 -0.44,1.7 -0.74,1.7
  Top Layer region: 0.44,1.4 0.74,1.4 0.74,1.7 0.44,1.7
  silkscreen extent -2.05,-2 2,2, body extent -1.7,-1.7 1.7,1.7, height 1.12

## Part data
C1 C19 C22 C30: "CAP, CERM, 1uF, 25V, +/-10%, X7R, 0603"
C2 C3 C21 C23 C26 C27: "CAP, CERM, 10uF, 25V, +/-10%, X5R, 1206"
C4: "CAP, OS-CON, 100uF, 20V, +/-20%, 0.024 ohm, 8x10 SMD"
C5: "CAP, OS-CON, 100uF, 16V, +/-20%, 0.035 ohm, 10x10.3 SMD"
C6: "CAP, CERM, 2.2uF, 25V, +/-10%, X7R, 1206"
C7 C8 C9 C10 C11 C12 C13: "CAP, CERM, 22uF, 25V, +/-10%, X5R, 1210"
C14 C15 C16 C17 C24 C25 C28 C31 C33 C34: "CAP, CERM, 0.1uF, 25V, +/-10%, X7R, 0603"
C18: "CAP, CERM, 2200pF, 25V, +/-10%, X7R, 0603"
C20: "CAP, CERM, 0.047uF, 25V, +/-10%, X7R, 0603"
C29: "CAP, CERM, 470pF, 50V, +/-5%, C0G/NP0, 0603"
C32 C35: "CAP, CERM, 0.01uF, 25V, +/-10%, X7R, 0603"
C36 C37 C38: "CAP, CERM, 100pF, 50V, +/-5%, C0G/NP0, 0603"
D1 D2: "Diode, Schottky, 30V, 0.2A, SOT-23"
D3 D4 D5: "LED, Green, SMD"
FID1 FID2 FID3 FID4 FID5 FID6: "Fiducial mark.  There is nothing to buy or mount."
J1 J2 J3: "TERMINAL BLOCK 5.08MM VERT 2POS"
J4 J5: "Terminal Block, 6A, 3.5mm Pitch, 4-Pos, TH"
J6: "Terminal Block, 6A, 3.5mm Pitch, 3-Pos, TH"
L1: "Inductor, Shielded, Powdered Iron, 2.2 µH, 10.5 A, 0.0137 ohm, SMD"
LBL1: library part THT-14-423-10, "Thermal Transfer Printable Labels, 0.650\" W x 0.200\" H - 10,000 per roll"
Logo1: library part TI_Logo, "Texas Instrument Corporate Signature"
Logo2: library part EURoHS_Exempt
Logo3: library part FCC_disclaimer, "FCC_disclaimer"
NT1 NT2 NT3 NT4 NT5 NT6 NT7: "Single point connection between nets."
Q1 Q7: "MOSFET, N-CH, 30V, 27A, SON 3.3x3.3mm"
Q2 Q5: "MOSFET, N-CH, 30V, 47A, SON 3.3x3.3mm"
Q3: "MOSFET, P-CH, -20 V, -60 A, VSON-CLIP-8"
Q4: library part SI7141DP-T1-GE3, "MOSFET, P-CH, -20V, 60A, PowerPAK SO-8"
Q6: "MOSFET, N-CH, 50V, 0.2A, SOT-323"
Q8: "MOSFET, N-CH, 60V, 0.26A, SOT-23"
R1 R5: "RES, 0.01 ohm, 1%, 1W, 1206"
R2 R3: "RES, 3.9 ohm, 5%, 0.25W, 1206"
R4 R8 R9 R18 R19 R20 R21 R29: "RES, 0 ohm, 5%, 0.1W, 0603"
R6: "RES, 4.7 ohm, 5%, 0.1W, 0603"
R7 R11 R25 R26 R30: "RES, 10Meg ohm, 5%, 0.1W, 0603"
R10: "RES, 430k ohm, 1%, 0.1W, 0603"
R12 R13: "RES, 4.02k ohm, 1%, 0.1W, 0603"
R14: "RES, 316k ohm, 1%, 0.1W, 0603"
R15 R27 R39 R41: "RES, 100k ohm, 1%, 0.1W, 0603"
R16: "RES, 10.0 ohm, 1%, 0.25W, 1206"
R17: "RES, 66.5k ohm, 1%, 0.1W, 0603"
R22 R28 R33 R35 R36 R37: "RES, 10.0k ohm, 1%, 0.1W, 0603"
R23: "RES, 10.0 ohm, 1%, 0.1W, 0603"
R24: "RES, 0 ohm, 5%, 0.125W, 0805"
R31: "RES, 499k ohm, 1%, 0.1W, 0603"
R32: "RES, 140k ohm, 1%, 0.1W, 0603"
R34: "RES, 30.1k ohm, 1%, 0.1W, 0603"
R38: "RES, 49.9k ohm, 1%, 0.1W, 0603"
R40: "RES, 3.0Meg ohm, 5%, 0.1W, 0603"
R42: "RES, 1.00Meg ohm, 1%, 0.1W, 0603"
R43 R44 R45: "RES, 2.00k ohm, 1%, 0.1W, 0603"
R46: "RES, 3.01Meg ohm, 1%, 0.1W, 0603"
S1: "DIP Switch, 4 position slide actuator, SPST, SMD"
TP1: "Compact Probe Tip Circuit Board Test Points, TH, 25 per"
TP2 TP3 TP4 TP5 TP6 TP7 TP8 TP9 TP10 TP11 TP12 TP13 TP14 TP15 TP16: "Test Point, Miniature, SMT"
U1: library part bq24770RUY, "NVDC Battery Charge Controller with SMBus, RUY0028A"
U2: "Single-Channel, Adjustable Supervisory Circuit in Ultra-Small Package, DRY0006A"
ZZ1: library part AssemblyNoteLabel
ZZ2 ZZ3 ZZ4: library part AssemblyNote

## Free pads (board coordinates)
  round 34 hole 16: 0(2155,1080)

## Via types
v1: diameter 30, hole 12, Top Layer to Bottom Layer, tented both sides, 239 vias
v2: diameter 34, hole 16, Top Layer to Bottom Layer, tented both sides, 48 vias
v3: diameter 19.68, hole 7.87, Top Layer to Bottom Layer, 15 vias
v4: diameter 28, hole 8, Top Layer to Bottom Layer, tented both sides, 12 vias
v5: diameter 40, hole 16, Top Layer to Bottom Layer, 5 vias
v6: diameter 19.68, hole 7.87, Top Layer to Bottom Layer, tented both sides, 1 vias
v7: diameter 28, hole 10, Top Layer to Bottom Layer, tented both sides, 1 vias
v8: diameter 26, hole 10, Top Layer to Bottom Layer, tented both sides, 1 vias

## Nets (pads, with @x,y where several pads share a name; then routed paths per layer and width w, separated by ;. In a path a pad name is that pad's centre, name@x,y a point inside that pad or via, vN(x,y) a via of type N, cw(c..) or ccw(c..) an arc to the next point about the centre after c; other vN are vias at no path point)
3V3: J5.4 R22.2 R33.2 R35.2 R36.2 R37.1 R43.1 R44.1 R45.2 | length 2456.6
  Top Layer w10: 965,871 966,872 v2(1012,872) ; R43.1@1431.5,789 1431.5,824.5 v2(1420,836) 1420,845 1410,855 1410,900 1443,933 1443,1064 1444,1065 R37.1@1437,1072
  Top Layer w40: 611.5,1124 575,1124 575,1000 965,1000 ; J5.4@963.39,155 965,156.61 965,871 965,1000 ; R35.2@1175,1088.5 1066,1088.5 1066,1031 1035,1000 965,1000
  MidLayer2 w10: v2(1012,872) 1013,873 1222,873 1259,836 v2(1420,836)
ACDET06: C34.1 R10.1 R17.2 TP7.1 U1.6 | length 1905.8
  Top Layer w8: R17.2@756,1230.5 756,1261 ; 875,1255 899,1255 947.5,1303.5 U1.6@976.26,1303.5
  Top Layer w10: TP7.1@455,470 v1(455,555) ; R10.1@524,1604.49 524,1527 458,1461 458,1417.5 457,1416.5 482.5,1391 532,1391 543,1380 543,1316 565.5,1293.5 645,1293.5 645,1265 649,1261 756,1261 869,1261 875,1255 v2(875,1230)
  MidLayer2 w10: v1(455,555) 522,555 817,850 817,1173.6 873.4,1230 v2(875,1230)
ACDRV04: R12.1 TP6.1 U1.4 | length 1350.8
  Top Layer w8: R12.1@762.5,1294 763.5,1293 802,1293 824,1315 ; v2(845,1295) 844,1295 824,1315 ; U1.4@976.26,1335 922.18,1335 921.18,1336 898.82,1336 897.82,1335 844,1335 824,1315
  Top Layer w10: TP6.1@310,465 v1(310,555)
  MidLayer2 w10: v1(310,555) 364,555 765,956 765,1225 835,1295 v2(845,1295)
ACDRVX: C18.2 C25.2 Q6.3 R6.1 R12.2 | length 732.3
  Top Layer w8: C18.2@581,1613.97 582.73,1612.24 582.73,1583.76 610,1556.5 C25.2@610.5,1557 ; Q6.3@674.5,1215 688,1215 712,1239 v2(712,1228) ; v7@682,1290 v7@684,1290 ; v7@686,1288 v7@684,1290 ; v7@686,1290 v7@684,1290 ; R6.1@695.5,1587 640.5,1587 C25.2@610.5,1557 ; R12.2@713.5,1295 714,1295 730,1311 730,1482 729.81,1482.19 729.81,1551.19 724,1557 C25.2@610.5,1557
  Top Layer w25: v7(684,1287) 712,1287 713,1288 712,1289 R12.2@712,1294
  MidLayer2 w8: v7@686,1290 682,1290 682,1258 v2(712,1228)
ACN01: R9.1 U1.1 | length 136.1
  Top Layer w8: 879.49,1395 892.24,1382.24 U1.1@976.26,1382.24
  Top Layer w10: 879.49,1395 880,1395 R9.1@880,1428.5
ACOK05: J4.4 Q8.1 R22.1 U1.5 | length 1875.6
  Top Layer w8: J4.4@152,756.61 88,820.61 88,1225 99,1236 221,1236 240,1217 254,1217 309,1162 658,1162 710.5,1109.5 ; J4.4@155,755 170,755 245,680 Q8.1@335.57,680 ; R22.1@635,1063 664,1063 710.5,1109.5 ; v2(798,1197) 796,1195 796,1124 781.5,1109.5 710.5,1109.5 ; v2@910,1309 910,1310 931.62,1310 940.87,1319.25 U1.5@976.26,1319.25
  MidLayer2 w8: v2(798,1197) v2(909,1308) v2@910,1309
ACP02: R8.1 U1.2 | length 212.8
  Top Layer w8: 833.5,1366.5 U1.2@976.26,1366.5
  Top Layer w10: R8.1@816.46,1429.53 825,1420.98 825,1375 833.5,1366.5
BAT: C33.1 D2.2 J3.2 Q3.1 Q3.2 Q3.3 Q4.5 Q4.6 Q4.7 Q4.8 Q4.9 R23.2 R29.2 | length 2882.2
  Top Layer w8: 737.19,1888.73 737.19,1907 ; 737.46,1888.87 784.74,1841.6 801.4,1841.6 D2.2@802.4,1842.6
  Top Layer w10: 737,1902 737,1952 750,1965 1010,1965 1140,1835 v2(1510,1835) ; v2(1670,1805) 1686.81,1788.19 2116.81,1788.19 2125,1780 Q4.9@2125,1642.5 ; R23.2@1802.5,1066 v1@1844,1066 ; R29.2@1857,1031 1850,1031 1844,1037 v1@1844,1066 ; v1(1857,1067) v1@1845,1067 ; v2(1949,1127) 1949,1129 1880,1129 1866.25,1115.25 1866.25,1113.25 1859.75,1106.75 1859.75,1081.75 v1@1845,1067 ; v2(2102,1312) 2134,1312 2144,1322 2144,1352 Q3.1@2150,1358 ; v1@1844,1066 v1@1845,1067
  Top Layer w100: Q4.9@2125,1642.5 2296.5,1642.5 2338,1601
  Top Layer w154: 2338,1601 J3.2@2614,1601
  MidLayer2 w10: v2(1510,1835) 1505,1830 1530,1805 v2(1670,1805) ; v2(1949,1127) 1949,1201 2059,1311 2099,1311 v2@2102,1308
  other v1: 2217,1360 2249,1360 2198,1400 2227,1413
  other v4: 2065,1600 2105,1600 2145,1600 2185,1600 2065,1640 2105,1640 2145,1640 2185,1640 2065,1680 2105,1680 2145,1680 2185,1680
  other v5: 2377,1552 2551,1599 2379,1651
BAT17: R23.1 TP12.1 U1.17 | length 1508.7
  Top Layer w8: v1(1705,1111) 1704,1110 1704,1101 1704.5,1101 R23.1@1739.5,1066
  Top Layer w10: U1.17@1133.74,1319.25 1179.25,1319.25 ; 1181,1320 1180,1320 1179.25,1319.25 ; TP12.1@1605,460 v1(1670,460) ; v1(1705,1111) 1705,1151 1655,1201 1329.18,1201 1321.18,1193 1294,1193 1229,1258 1229,1306 1215.75,1319.25 1179.25,1319.25
  MidLayer2 w10: v1(1670,460) 1670,495 1675,500 1675,930 1691,946 1691,1097 v1(1705,1111)
BATDRV18: R21.1 TP13.1 U1.18 | length 1617.7
  Top Layer w8: U1.18@1133.74,1335 1225,1335
  Top Layer w10: 1225,1335 1250,1310 1250,1265 1255,1260 1293.52,1260 1302,1251.52 v1(1302,1223) ; TP13.1@1765,460 v1(1825,460)
  MidLayer2 w10: v1(1302,1223) 1302,1222 1307,1217 1313,1223 1352,1223 1359,1216 1753,1216 1890,1079 1890,640.6 1891,639.6 1891,616.4 1890,615.4 1890,525 v1(1825,460)
BATPRES15: C35.1 D3.2 R24.1 R25.2 R27.2 TP10.1 U1.15 | length 2507.7
  Top Layer w8: U1.15@1133.74,1287.76 1152.24,1287.76 ; v2(1333,721) 1333,724 v2@1336,727 ; v2(1435,695) 1535,695 ; D3.2@1499.53,879 1537,879 ; v2@1533,1160 1537,1156 C35.1@1574.5,1156 ; 1536,1040 1537,1039 1537.5,1038.5 R27.2@1582,1038.5
  Top Layer w10: 1152.24,1287.76 1287,1153 1526,1153 v2(1532,1159) ; TP10.1@1275,490 1275,666 v2@1329.5,720.5 ; v2(1537,1098) 1537,1039 1537,879 1537,656 1598,595 2353,595 R24.1@2425.5,667.5
  MidLayer2 w8: v2(1333,721) v2@1333,722 ; v2@1335,722 1338,725 1405,725 v2(1435,695) ; v2@1532,1103 v2(1537,1098)
  MidLayer2 w25: v2@1532,1103 v2(1532,1159)
BTST25: R4.1 U1.25 | length 82.9
  Top Layer w8: U1.25@1055,1413.74 1055,1440
  Top Layer w12: R4.1@1035,1486 1042,1479 1046,1479 1046,1461 1055,1452 1055,1440
CELL16: R26.1 R30.2 TP11.1 U1.16 | length 1529.2
  Top Layer w8: U1.16@1133.74,1303.5 1134.24,1303 1182,1303 1195,1290 1195,1269 1291,1173 1343.5,1173 1354.5,1184 1512,1184 1514,1186 1600,1186 1607,1179 1607,1132 1628.75,1110.25 1664.75,1110.25 1690,1085 1690,1023.5 1706.5,1007 1706.5,937 1705.5,936 1669.5,972 v2@1664,972
  Top Layer w10: TP11.1@1435,460 v1(1435,545)
  MidLayer2 w8: v1(1435,545) 1435,621 1584,770 1584,913 1643,972 v2(1663,972) v2@1664,972
CMPIN13: J6.3 R40.2 S1.8 U1.13 | length 3757
  Top Layer w8: 1087,1237 U1.13@1087,1257 ; S1.8@1969.5,1016.7 1969.5,1071 R40.2@1970.5,1072 ; R40.2@1970,1072 R40.2@1970.5,1072 ; R40.2@1981,1082 1984,1079 1977,1072 R40.2@1970.5,1072
  Top Layer w10: 1087,1237 1104,1220 1165,1220 1275,1110 1385,1110 1390,1105 1390,945 1361,916 1361,702 1504,559 2447,559 2530,642 2530,890 2529.19,890.81 2529.19,1074.19 2530,1075 2425,1180 2021,1180 1981,1140 R40.2@1981,1082 ; 2520,625 2641,504 J6.3@2641,151
CMPIN13SW: R32.1 R39.2 S1.1 | length 271.1
  Top Layer w8: R32.1@1834.5,754 1834.5,693 1873.69,653.8 ; v2(1863,628) 1852,628 1850,630 1873.8,653.8 S1.1@1981,653.8
CMPOUT14: J6.1 R37.2 R40.1 S1.7 U1.14 | length 3699.6
  Top Layer w8: U1.14@1103,1256 1113.81,1256 1114.07,1256.26 1130.33,1240 ; R40.1@2032.5,1071 2067,1036.5 2067,994.2 S1.7@2071,990.2
  Top Layer w10: 1130.33,1240 1170,1240 1280,1130 1435.56,1130 R37.2@1440,1125.56 ; 1410,1130 1410,935 1385,910 1385,791.4 1407,769.4 1407,683.4 1504,586.4 1504,586 1511,579 2439,579 2493,633 2493,696 v2@2496,699 ; R40.1@2032.5,1071 2038,1076.5 2038,1103 2090,1155 2417,1155 2499.5,1072.5 v2@2499.5,707.5 ; J6.1@2369,155 2369,319 2515,465 v2@2515,561
  MidLayer2 w10: v2@2497,700 2515,682 v2@2515,564
  other v2: 2516,562 2496,701
CMSRC03: R13.1 R19.1 TP5.1 U1.3 | length 1762.6
  Top Layer w8: R13.1@584.5,1434 v2@619,1434 ; v2@621,1432 v2(621,1433) ; R19.1@760.5,1345 785,1345 790,1340 v2(810,1340) 820.75,1350.75 U1.3@976.26,1350.75 ; R19.1@761.5,1349 762.5,1348 R19.1@765.24,1350.75
  Top Layer w10: TP5.1@145,465 v1(145,555)
  MidLayer2 w8: v2(621,1433) 621,1432 633,1420 730,1420 v2(810,1340)
  MidLayer2 w10: v1(145,555) 202,555 472.5,825.5 ; 473,825 602,825 675.5,898.5 675.5,1028.5 740,1093 740,1290 790,1340 v2(810,1340)
GND: C16.2 C17.2 C19.2 C28.2 C31.2 C32.1 C33.2 C34.2 C35.2 C36.2 C37.2 C38.2 J4.2 J5.1 J6.2 NT1.1 NT2.1 NT3.1 NT4.1 NT5.1 NT6.1 NT7.1 Q8.2 R15.2 R17.1 R19.2 R27.1 R30.1 R34.2 R38.1 R39.1 R41.1 R42.1 TP2.1 TP4.1 U2.2 | length 239.8
  Top Layer w20: C17.2@696.5,1519 696.5,1346 R19.2@697.5,1345 ; v1@1763,1160 1804,1119 C33.2@1811.44,1119
  other v1: 2594,71 2415,72 800,74 595,75 697,75 2276,77 1228,83 1337,83 1452,83 1552,83 1657,83 1891,83 1758,84 2008,85 116,86 231,86 2144,86 2752,86 344,87 457,88 1101,92 65,144 2751,184 65,233 2751,290 65,325 420,350 490,350 610,350 760,350 870,350 156,352 260,354 354,354 2750,399 382,431 241,434 632,438 527,442 720,453 879,454 805,457 2749,516 2748,598 1712,638 1770,639 104,653 203,674 2750,728 253,761 1640,814 2749,824 117,827 251,856 1330,865 1962,917 2748,924 1796,943 245,955 121,964 2748,1020 736,1041 986,1042 2660,1058 247,1062 999,1081 2568,1108 2746,1122 1678,1139 1762,1160 700,1170 241,1186 1823,1188 555,1193 2456,1196 461,1199 2732,1199 2544,1200 242,1257 460,1274 577,1322 241,1351 399,1351 461,1351 329,1352
  other v8: 673,1325
HIDRV26: C15.1 Q2.4 U1.26 | length 892.2
  Top Layer w8: v1@984,1478.39 v1@984,1482 ; v1@985,1488 985,1483 990,1483 1039,1434 1039,1413.99 U1.26@1039.25,1413.74
  Top Layer w10: v1@985,1488 969,1504 969,1528.77 971,1530.77 971,1650 1022,1701 1142.26,1701 v1@1171.26,1672
  Top Layer w20: Q2.4@1303.64,1694 1303.64,1697 1324.64,1676 v2(1362,1676)
  MidLayer2 w10: v1@1171.26,1672 1171.26,1671.26 v1@1175,1675
  MidLayer2 w12: v1@1175,1675 v2@1362,1675
  Bottom Layer w20: v2@1362,1672 v2(1362,1676) ; v2@1363.5,1676 C15.1@1363.5,1795
  other v1: 984,1483 1171.26,1678
IADP07: C37.1 TP8.1 U1.7 | length 833.5
  Top Layer w8: v2@845,1150 v2@845,1154.57 ; v2(845,1162) v2@845,1154.57 ; U1.7@965,1285 965,1276.5 900,1211.5 900,1151.5 884.5,1167 857.43,1167 v2@845,1154.57
  Top Layer w10: TP8.1@838.89,575 845,581.11 v1(845,660)
  MidLayer2 w10: v1@845,655 v1(845,660) v2(845,1162)
IBAT08: C36.1 TP9.1 U1.8 | length 1041.8
  Top Layer w8: v2@930,1200 955,1200 ; C36.1@955,1151.5 955,1200 ; U1.8@1008,1256 1007.74,1256.26 981.26,1256.26 955,1230 955,1200
  Top Layer w10: TP9.1@1120,455 v1(1120,540)
  MidLayer2 w10: v2@930,1200 875,1145 875,805 1120,560 v1(1120,540) v1@1120,535
  other v2: 929,1201
LODRV23: C29.1 Q5.4 U1.23 | length 478.6
  Top Layer w8: U1.23@1086.5,1413.74 1086.5,1434.5 ; 1087,1431 1087,1435 1091.49,1439.49 1108.02,1439.49 1108.51,1439 1118.64,1439 1123.64,1434 1150,1434 v1@1159,1443
  Top Layer w10: v1@1165,1445 v1(1169,1449) 1183,1435 C29.1@1243.5,1435 ; Q5.4@1312,1506.34 Q5.4@1313.39,1506.34 v2@1360.34,1506.34
  MidLayer2 w10: 1177,1462 1177,1497 1205,1525 1323.74,1525 1340.74,1508 v2(1363,1508)
NetC1_1: C1.1 C2.1 C3.1 C14.2 C17.1 Q2.5 Q2.6 Q2.7 Q2.8 Q2.9 R1.2 R9.2 | length 425.3
  Top Layer w10: C17.1@759.5,1519 794.5,1554 880,1554 ; R9.2@880,1491.5 880,1554 ; C14.2@880,1621 880,1554 ; C14.2@885.56,1624 936,1624 C1.1@939,1621 ; R1.2@943.54,1701.02 956.02,1701.02 R1.2@965,1710
  Top Layer w30: C1.1@928,1622.56 R1.2@928,1703.54
NetC4_1: C4.1 C5.1 C7.1 C8.1 C9.1 C10.1 C11.1 C12.1 C13.1 C21.1 C24.1 C31.1 J2.2 L1.2 R5.1 R18.2 | length 655.6
  Top Layer w10: R18.2@1353.86,1385 1517.81,1385 1535.23,1367.58 1648.84,1367.58 1692.09,1410.83 C21.1@1692.09,1415 ; R18.2@1356.51,1375 R18.2@1364.7,1383.19 ; R5.1@1756,1421 1813,1364 1813,1261 1823,1251 C24.1@1901,1251 ; C31.1@1849.5,1250 C31.1@1850,1250.5
  other v1: 2185,2145 2235,2145 2285,2145 2335,2145 2395,2145 2466,2145 2505,2145
NetC6_2: C6.2 R2.2 R3.2 | length 241.7
  Top Layer w25: 452.09,1855 462.09,1865 ; C6.2@501.91,1865 C6.2@507.41,1859.5
  Top Layer w50: 452.09,1855 R3.2@452.09,2035
  Top Layer w75: 462.09,1865 C6.2@501.91,1865
NetC20_1: C20.1 D1.3 R4.2 | length 350
  Top Layer w10: C20.1@1147,1555.5 C20.1@1155.5,1564
  Top Layer w20: C20.1@1155.5,1564 v2@1192,1564
  Top Layer w25: v1@1008,1578 1008,1571 R4.2@1036,1543
  MidLayer2 w25: v1@1010,1569 1026,1553 1182,1553 v2(1192,1563)
  Bottom Layer w23: D1.3@1139,1586 D1.3@1144.4,1586 1170,1586 v2@1192,1564
  other v1: 1011,1577
NetC23_1: C23.1 C24.2 C26.1 C27.1 C28.1 Q3.5 Q3.6 Q3.7 Q3.8 Q3.9@2069.41,1395 Q4.1 Q4.2 Q4.3 R5.2 R7.2 R20.2 | length 1401.1
  Top Layer w10: R20.2@1356.51,1315 1387,1315 1411,1291 1554.5,1291 1583.5,1262 1658,1262 1659,1261 1660.25,1261 1672.25,1249 1677.25,1249 1701.25,1225 1927.56,1225 C24.2@1953,1250.44 ; v2(1840,1379.57) 1875.43,1415 R5.2@1882.09,1415 ; C23.1@1882.09,1320 1894.09,1308 1923,1308 1953,1278 C24.2@1953,1254 ; C28.1@1957.56,1197 1957.56,1251.56 C24.2@1959,1253 ; C24.2@1959,1246 R7.2@2074.5,1246 ; Q3.9@2052.24,1430 2055.63,1433.39 2082.6,1406.42 Q3.9@2082.6,1395
  Top Layer w20: 1995,1381 2068.6,1381 Q3.9@2082.6,1395 ; 1995,1408 1995.2,1407.8 2055.63,1407.8 2068.43,1395 Q3.9@2082.6,1395 ; 1995,1430 2012.41,1434.39 2041.04,1434.39 Q3.9@2052.24,1430 ; 2004,1354 2006,1356 2078,1356 2081,1359 2082,1359 2082.6,1359.6 Q3.9@2082.6,1395
  other v3: 2051.61,1356.61 2086.1,1356.61 2068.86,1395 2103.35,1395 2051.61,1433.39 2086.1,1433.39
  other v6: 2034.37,1395
NetC38_1: C38.1 U2.5 | length 86.5
  Top Layer w8: U2.5@1789.16,819 1821,819 1831,829 C38.1@1831,869.5
NetD2_3: D2.3 R16.2 | length 96.9
  Top Layer w10: D2.3@765,1904.78 775.22,1915 843.5,1915 R16.2@853.5,1905
NetD3_1: D3.1 R43.2 | length 111.3
  Top Layer w10: D3.1@1445.47,880 1455,870.47 1455,834 1494.5,794.5 R43.2@1494.5,789
NetD4_1: D4.1 R44.2 | length 66.3
  Top Layer w10: R44.2@512.5,1040 512.5,1098.5 D4.1@518,1104
NetD5_1: D5.1 R45.1 | length 366.9
  Top Layer w10: D5.1@539.53,695 R45.1@906.44,695
NetD5_2: D5.2 Q8.3 | length 97.7
  Top Layer w10: Q8.3@406.43,645 420,645 445,670 465.47,670 D5.2@485.47,690
NetQ3_4: Q3.4 Q4.4 R7.1 R11.2 R21.2 | length 1290.1
  Top Layer w10: R21.2@1356.51,1260 1370.51,1246 1648,1246 1649,1245 1653.63,1245 1665.63,1233 1670.63,1233 1696.63,1207 1754,1207 1800,1161 1974,1161 2018,1205 2125,1205 2131.5,1211.5 R7.1@2131.5,1240 ; R7.1@2131.5,1246 2167,1281.5 2167,1297 v2(2172,1292) ; R7.1@2141.5,1240 R11.2@2198.5,1240
  Top Layer w19: Q3.4@2151.5,1433.4 2181.6,1433.4
  Top Layer w20: 2181.6,1433.4 2182,1433 v2@2200,1451 ; v2@2200,1462 Q4.4@2200,1510.5
  MidLayer2 w10: v2(2172,1292) 2170,1294 2170,1432 2200,1462 v2(2207,1462)
NetQ6_1: Q6.1 R42.2 R46.1 | length 181.7
  Top Layer w8: R42.2@523.5,1355 523.5,1305 515,1296.5 533.5,1278 574.09,1278 Q6.1@611.5,1240.59
NetR24_2: R24.2 S1.2 S1.3 | length 486
  Top Layer w10: S1.2@2084,653.8 S1.2@2085,653.8 S1.3@2183,653.8 ; S1.3@2187,649 2189,647 2189,620 2196,613 2325,613 2338,626 ; 2337,627 2338,628 2338,731 2356,749 R24.2@2426,749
